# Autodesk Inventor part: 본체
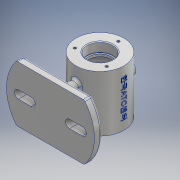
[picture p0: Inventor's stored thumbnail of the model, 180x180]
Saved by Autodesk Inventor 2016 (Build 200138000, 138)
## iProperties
Created: 2017-12
Part Number: 본체
Material: 알루미늄 6061
Document SubType Name: Modeling
Designer: 605-03
Density: 2.7 g/cm^3
Appearance: 알루미늄 - 평지
Mass: 464.488 g
Surface Area: 487.59 cm^2
Volume: 172.033 cm^3
Author: 605-03
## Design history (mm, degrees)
sketch "스케치1"
  geometry: L1 (0, 0)-(30, 0); L2 (30, 0)-(30, -70); L3 (30, -70)-(0, -70); L4 (0, 0)-(0, -70); L5 (16, 0)-(16, -11.7); L6 (15.7, -12)-(14, -12); L7 (14, -12)-(14, -15); L8 (14, -15)-(22, -15); L9 (25, -18)-(25, -52); L10 (22, -55)-(14, -55); L11 (14, -55)-(14, -58); L12 (14, -58)-(15.7, -58); L13 (16, -58.3)-(16, -70); A1 r 0.3 centre (15.7, -58.3) between (16, -58.3) and (15.7, -58); A2 r 0.3 centre (15.7, -11.7) between (15.7, -12) and (16, -11.7); A3 r 3 centre (22, -18) between (25, -18) and (22, -15); A4 r 3 centre (22, -52) between (22, -55) and (25, -52); 4 further points
  constraints: 26 end point, 10 perpendicular, 10 point on line, 8 point on circle, 8 tangent, 4 centre point, 2 vertical, 1 equal radius, 1 horizontal
  dimensions: "d0" = 60 diameter of L2 L4; "d1" = 70 distance of L1.start L3.end; "d2" = 12 distance of L5.start point (16, -12); "d3" = 12 distance of point (16, -58) L13.end; "d4" = 40 distance of point (25, -15) point (25, -55); "d5" = 3 distance of L10.end L11.end; "d6" = 32 diameter of L5 L4; "d7" = 28 diameter of L7 L4; "d8" = 50 diameter of L9 L4; "d9" = 32 diameter of L13 L4; "d10" = 28 diameter of L11 L4; "d11" = 0.3 radius of A1; "d12" = 3 radius of A3; "d13" = 3 radius of A4
revolve "회전1" sketch "스케치1" stored, may be unused: angle "d14" = 90 deg
sketch "스케치2" dims "d15" = 46
  geometry: C1 r 30 at (0, 0) reference; C2 r 16 at (0, 0) reference; 5 further points
  constraints: 2 vertical alignment, 1 coincident, 6 other
  dimensions: "d18" = 360 deg dimension on point (0, 0) point (0, 23) (derived)
hole "구멍1" sketch "스케치2" at (0, 23), (-19.919, -11.5), (19.919, -11.5) diameter "d20" = 3.242; stored, may be unused: countersink angle "d24" = 90 deg, drill point angle "d26" = 118 deg; dims "d21" = 8, "d22" = 4, "d23" = 2, "d25" = 10
sketch "스케치3" dims "d27" = 46
  geometry: C1 r 30 at (0, 0) reference; C2 r 16 at (0, 0) reference; 5 further points
  constraints: 2 vertical alignment, 1 coincident, 6 other
  dimensions: "d30" = 360 deg dimension on point (0, 0) point (0, 23) (derived)
hole "구멍2" sketch "스케치3" at (0, 23), (-19.919, -11.5), (19.919, -11.5) diameter "d32" = 3.242; stored, may be unused: countersink angle "d36" = 90 deg, drill point angle "d38" = 118 deg; dims "d33" = 8, "d34" = 4, "d35" = 2, "d37" = 10
node "작업 평면2"
sketch "스케치6"
  geometry: L1 (42.426, -70)-(-42.426, -70); L2 (42.426, 0)-(-42.426, 0); L3 (-30, 0)-(30, 0) reference; L4 (-30, -70)-(30, -70) reference; L5 (0, 0)-(0, -70); L6 (-16, -70)-(16, -70) reference; A1 r 55 centre (0, -35) between (-42.426, 0) and (-42.426, -70); A2 r 55 centre (0, -35) between (42.426, -70) and (42.426, 0); 2 further points
  constraints: 6 end point, 4 point on circle, 3 midpoint, 2 centre point, 2 horizontal, 1 coincident, 1 vertical alignment
  dimensions: "d58" = 70 distance between parallel lines of L1 L2; "d59" = 35 distance from line of L2 A1.centre; "d60" = 110 diameter of A1; "d61" = 55 radius of A2
extrude "돌출2" join sketch "스케치6" distance "d62" = 10; taper "d63" = 0 deg
sketch "스케치7"
  geometry: L1 (42.426, 0)-(-42.426, 0) reference; L2 (-42.426, 70)-(42.426, 70) reference; L3 (42.426, 0)-(-42.426, 0) reference; L4 (-42.426, 0)-(-42.426, 70); L5 (-42.426, 70)-(42.426, 70) reference; L6 (42.426, 70)-(42.426, 0); L7 (0, 20)-(0, 50); L8 (5, 20)-(5, 50); L9 (-5, 50)-(-5, 20); L10 (-42.426, 35)-(42.426, 35); L11 (-40, 35)-(-24, 35); L12 (-40, 30)-(-24, 30); L13 (-24, 40)-(-40, 40); L14 (24, 35)-(40, 35); L15 (24, 30)-(40, 30); L16 (40, 40)-(24, 40); A1 r 55 centre (0, 35) between (42.426, 0) and (42.426, 70) reference; A2 r 55 centre (0, 35) between (-42.426, 70) and (-42.426, 0) reference; A3 r 5 centre (0, 20) between (-5, 20) and (5, 20); A4 r 5 centre (0, 50) between (5, 50) and (-5, 50); A5 r 5 centre (-40, 35) between (-40, 40) and (-40, 30); A6 r 5 centre (-24, 35) between (-24, 30) and (-24, 40); A7 r 5 centre (24, 35) between (24, 40) and (24, 30); A8 r 5 centre (40, 35) between (40, 30) and (40, 40); 5 further points
  constraints: 30 end point, 12 point on circle, 12 tangent, 6 centre point, 6 midpoint, 3 parallel, 2 horizontal, 2 horizontal alignment, 2 perpendicular, 1 coincident, 1 vertical
  dimensions: "d64" = 10 diameter of A4; "d65" = 30 distance of L7.start L7.end; "d66" = 10 diameter of A6; "d67" = 16 distance of L11.end L11.start; "d68" = 24 distance of A1.centre L11.end; "d69" = 10 diameter of A8; "d70" = 16 distance of L14.end L14.start; "d71" = 24 distance of A1.centre L14.start
  node "절단 모서리 투영4"
extrude "돌출3" join sketch "스케치7" stored distance "d72" = 10; taper "d73" = 0 deg
extrude "돌출4" cut sketch "스케치7" stored distance "d74" = 10; taper "d75" = 0 deg
node "작업 평면3"
sketch "스케치8"
  geometry: C1 r 8 at (0, -35); 1 further point
  constraints: 1 centre point, 1 vertical alignment
  dimensions: "d77" = 16 diameter of C1; "d78" = 35 distance of point (0, 0) C1.centre
extrude "돌출5" join sketch "스케치8" stored distance "d79" = 10; taper "d80" = 0 deg
hole "구멍3" diameter "d83" = 8; stored, may be unused: countersink angle "d87" = 90 deg, drill point angle "d89" = 0 deg; dims "d81" = 10, "d82" = 10, "d84" = 8, "d85" = 4, "d86" = 2, "d88" = 26
chamfer "모따기1" distance "d90" = 1; stored, may be unused: second distance "d91" = 2, angle "d92" = 45 deg
chamfer "모따기2" distance "d93" = 1; stored, may be unused: second distance "d94" = 2, angle "d95" = 45 deg
chamfer "모따기3" distance "d96" = 1; stored, may be unused: second distance "d97" = 2, angle "d98" = 45 deg
fillet "모깎기1" dims "d99" = 3
node "작업 평면4"
node "작업 평면5"
sketch "스케치10"
  geometry: 2 further points
  constraints: 1 vertical alignment, 1 other
  dimensions: "d103" = 35 distance of point (0, 35) point (0, 0)
feature "엠보싱2" sketch "스케치10" dims "d0" = 60, "d1" = 70, "d2" = 12, "d3" = 12, "d4" = 40, "d5" = 3, "d6" = 32, "d7" = 28, "d8" = 50, "d9" = 32, "d10" = 28, "d11" = 0.3, "d12" = 3, "d13" = 3, "d104" = 0.5, "d105" = 0
node "솔리드1"
node "투영된 루프2"
node "절단 모서리 투영1"
node "절단 모서리 투영2"
other parameters: "d56" = -62, "d76" = 37
